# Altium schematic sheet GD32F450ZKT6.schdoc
size 127 x 101 mm
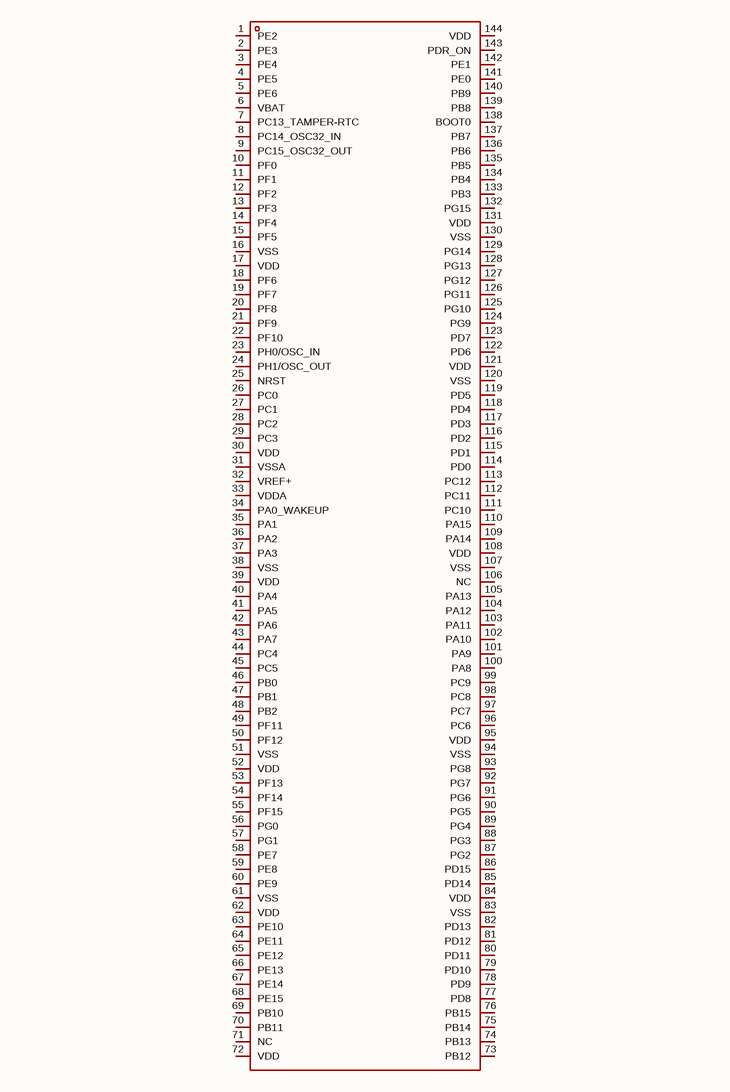
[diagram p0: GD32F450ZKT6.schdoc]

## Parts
U?  gd32f450zkt6  [LQFP-144_L20.0-W20.0-P0.50-LS22.0-BL]  (value not drawn)

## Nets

Not connected (* = marked no-connect by the designer): U? 1(PE2) 2(PE3) 3(PE4) 4(PE5) 5(PE6) 6(VBAT) 7(PC13_TAMPER-RTC) 8(PC14_OSC32_IN) 9(PC15_OSC32_OUT) 10(PF0) 11(PF1) 12(PF2) 13(PF3) 14(PF4) 15(PF5) 16(VSS) 17(VDD) 18(PF6) 19(PF7) 20(PF8) 21(PF9) 22(PF10) 23(PH0/OSC_IN) 24(PH1/OSC_OUT) 25(NRST) 26(PC0) 27(PC1) 28(PC2) 29(PC3) 30(VDD) 31(VSSA) 32(VREF+) 33(VDDA) 34(PA0_WAKEUP) 35(PA1) 36(PA2) 37(PA3) 38(VSS) 39(VDD) 40(PA4) 41(PA5) 42(PA6) 43(PA7) 44(PC4) 45(PC5) 46(PB0) 47(PB1) 48(PB2) 49(PF11) 50(PF12) 51(VSS) 52(VDD) 53(PF13) 54(PF14) 55(PF15) 56(PG0) 57(PG1) 58(PE7) 59(PE8) 60(PE9) 61(VSS) 62(VDD) 63(PE10) 64(PE11) 65(PE12) 66(PE13) 67(PE14) 68(PE15) 69(PB10) 70(PB11) 71(NC) 72(VDD) 73(PB12) 74(PB13) 75(PB14) 76(PB15) 77(PD8) 78(PD9) 79(PD10) 80(PD11) 81(PD12) 82(PD13) 83(VSS) 84(VDD) 85(PD14) 86(PD15) 87(PG2) 88(PG3) 89(PG4) 90(PG5) 91(PG6) 92(PG7) 93(PG8) 94(VSS) 95(VDD) 96(PC6) 97(PC7) 98(PC8) 99(PC9) 100(PA8) 101(PA9) 102(PA10) 103(PA11) 104(PA12) 105(PA13) 106(NC) 107(VSS) 108(VDD) 109(PA14) 110(PA15) 111(PC10) 112(PC11) 113(PC12) 114(PD0) 115(PD1) 116(PD2) 117(PD3) 118(PD4) 119(PD5) 120(VSS) 121(VDD) 122(PD6) 123(PD7) 124(PG9) 125(PG10) 126(PG11) 127(PG12) 128(PG13) 129(PG14) 130(VSS) 131(VDD) 132(PG15) 133(PB3) 134(PB4) 135(PB5) 136(PB6) 137(PB7) 138(BOOT0) 139(PB8) 140(PB9) 141(PE0) 142(PE1) 143(PDR_ON) 144(VDD)

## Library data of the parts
U? = gd32f450zkt6: CPU内核:ARM Cortex-M4;CPU最大主频:200MHz;CPU位数:32 Bit;; Manufacturer: GigaDevice(兆易创新); AddInBom: yes; ModelId: 4b55735481674d0c808bacd550892b80; ModelTransform: 866.14,866.14,0,0,0,0,0,0,0; CPU Maximum Speed: 200MHz; Core Size: 32 Bit; Program Storage Size: 512KB; Program Memory Type: FLASH; Number of I/O: 114; ADC (Bit): 12bit; Oscillator Type: 内置+外置; Voltage - Supply: 2.6V~3.6V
